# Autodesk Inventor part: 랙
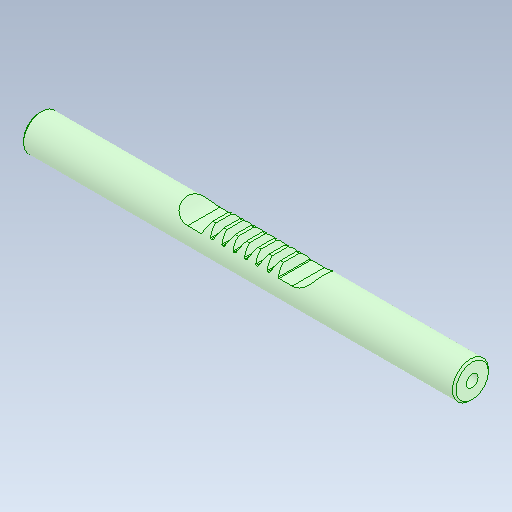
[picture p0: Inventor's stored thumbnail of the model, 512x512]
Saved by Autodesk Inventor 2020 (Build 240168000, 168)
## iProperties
Created: 2024-07
Part Number: 랙
Material: 강철, 탄소
Document SubType Name: Modeling
Designer: oem
Density: 7.85 g/cm^3
Appearance: 기본값
Author: jhkim
Sending System: Autodesk Inventor 2025
Preprocessor: ST-DEVELOPER v20
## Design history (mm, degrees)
feature "솔리드1"
node "솔리드2"
